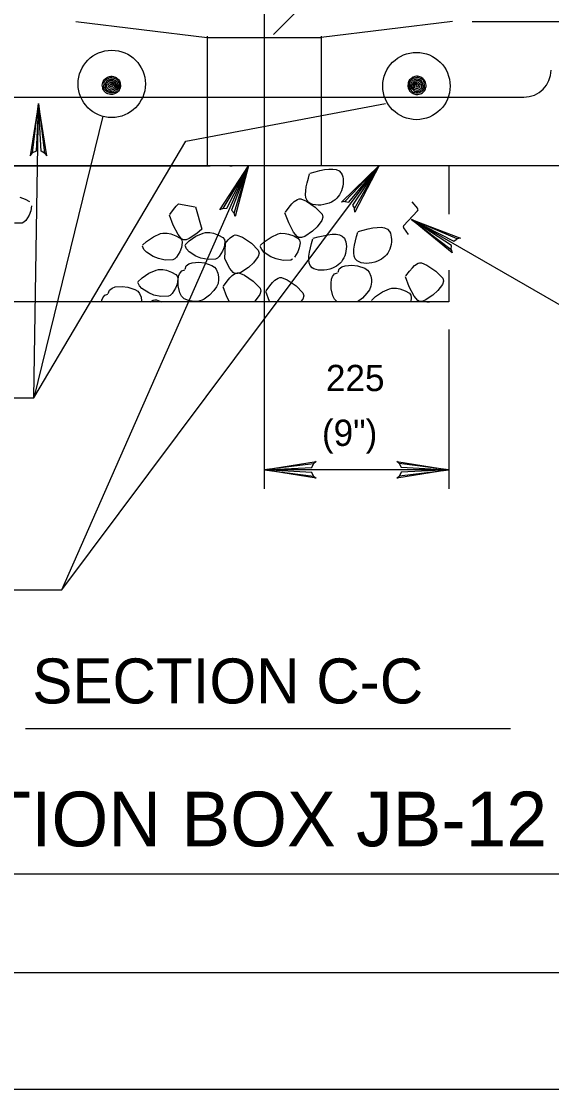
# Model space of a CAD drawing. Extents: x 638455 to 640199, y 298558 to 299152.
# Drawn here: x 639468.1 to 639536, y 298558.2 to 298695 of the extents above; entities that cross this region are included whole.
import ezdxf

# ---------------------------------------------------------------- set-up
doc = ezdxf.new("R2010")
doc.units = 0
for name, color, linetype in [('1', 7, 'Continuous'), ('2', 7, 'Continuous'), ('3', 7, 'Continuous'), ('PLT-BNDY', 7, 'Continuous')]:
    doc.layers.add(name, color=color, linetype=linetype)

msp = doc.modelspace()

# ---------------------------------------------------------------- linework, layer by layer
at = {"layer": '1'}
for p, q in [((639469.69, 298646.83), (639470.27, 298684.48)), ((639489.14, 298679.7), (639514.7, 298684.48)), ((639478.52, 298682.86), (639469.69, 298646.83)), ((639469.69, 298646.83), (639489.14, 298679.7)), ((639518.83, 298670.78), (639517.03, 298668.82)), ((639518.07, 298671.93), (639518.83, 298671.04)), ((639517.01, 298668.57), (639517.62, 298667.75))]:
    msp.add_line(p, q, dxfattribs=at)
msp.add_lwpolyline([(640119.61, 298573.25), (640119.61, 299137.25), (639333.61, 299137.25), (639333.61, 298573.25), (640119.61, 298573.25), (640119.61, 298599.61), (639919.61, 298599.61), (639919.61, 298664.29), (640119.61, 298664.29), (640119.61, 298693.25), (639919.61, 298693.25), (639919.61, 298573.25), (639998.42, 298573.25), (639998.42, 298599.61), (639998.42, 298573.25), (640075.42, 298573.25), (640075.42, 298599.61), (640075.42, 298587.29), (640119.61, 298587.29)], dxfattribs=at)
for centre in [(639479.66, 298687.01), (639518.68, 298686.74)]:
    msp.add_circle(centre, 4.31, dxfattribs=at)
for centre, start, end in [((639518.68, 298670.91), 317.4357, 40.7089), ((639517.18, 298668.68), 137.4357, 216.5044)]:
    msp.add_arc(centre, 0.2, start, end, dxfattribs=at)
at = {"layer": '2'}
for p, q in [((639500.37, 298693.34), (639515.41, 298708.39)), ((639499.18, 298704.79), (639499.18, 298643.37)), ((639475.08, 298695.02), (639491.9, 298692.96)), ((639523.29, 298695.02), (639506.47, 298692.96)), ((639525.82, 298695.02), (639581.13, 298695.02)), ((639491.9, 298693.11), (639491.9, 298676.53)), ((639491.9, 298692.96), (639506.47, 298692.96)), ((639506.47, 298693.11), (639506.47, 298676.53)), ((639465.64, 298685.31), (639532.43, 298685.31)), ((639543.38, 298676.53), (639454.98, 298676.53)), ((639457.42, 298676.53), (639492.28, 298676.53)), ((639473.27, 298622.22), (639497.18, 298676.53)), ((639494.8, 298676.53), (639495.08, 298676.53)), ((639522.81, 298676.53), (639522.81, 298670.34)), ((639554.38, 298648.67), (639518.04, 298669.66)), ((639522.81, 298663.17), (639522.81, 298659.11)), ((639522.81, 298659.11), (639414.14, 298659.11)), ((639522.81, 298655.56), (639522.81, 298635.17)), ((639460.96, 298646.83), (639469.69, 298646.83)), ((639499.18, 298643.37), (639499.18, 298635.17)), ((639522.81, 298637.61), (639499.18, 298637.61)), ((639464.54, 298622.22), (639473.27, 298622.22))]:
    msp.add_line(p, q, dxfattribs=at)
for points in [[(639471.07, 298678.15), (639470.61, 298678.38), (639470.27, 298684.48), (639471.07, 298678.15), (639471.35, 298677.82), (639470.27, 298684.48), (639469.97, 298678.39), (639469.52, 298678.17), (639470.27, 298684.48), (639469.22, 298677.82), (639469.52, 298678.17)], [(639473.27, 298622.22), (639513.92, 298676.56)], [(639493.9, 298671.06), (639494.41, 298671.09), (639497.18, 298676.53), (639493.9, 298671.06), (639493.51, 298670.88), (639497.18, 298676.53), (639495, 298670.84), (639495.32, 298670.45), (639497.18, 298676.53), (639495.46, 298670.02), (639495.32, 298670.45)], [(639509.49, 298671.97), (639510, 298671.88), (639513.92, 298676.56), (639509.49, 298671.97), (639509.07, 298671.88), (639513.92, 298676.56), (639510.51, 298671.5), (639510.74, 298671.05), (639513.92, 298676.56), (639510.78, 298670.6), (639510.74, 298671.05)], [(639467.91, 298672.51), (639468.57, 298672.27)], [(639468.57, 298672.27), (639469.12, 298671.97)], [(639503.01, 298671.94), (639503.44, 298672.23)], [(639503.44, 298672.23), (639503.66, 298672.29)], [(639503.66, 298672.29), (639503.87, 298672.28)], [(639503.87, 298672.28), (639504.58, 298672)], [(639469.28, 298670.75), (639469.08, 298670.22)], [(639469.37, 298671.42), (639469.28, 298670.75)], [(639487.11, 298670.3), (639487.57, 298670.92)], [(639487.57, 298670.92), (639487.93, 298671.36)], [(639487.93, 298671.36), (639488.22, 298671.65)], [(639488.22, 298671.65), (639490.34, 298671.26)], [(639490.37, 298671.26), (639491.19, 298668.42)], [(639501.9, 298670.59), (639502.36, 298671.21)], [(639502.36, 298671.21), (639502.72, 298671.66)], [(639502.72, 298671.66), (639503.01, 298671.94)], [(639504.58, 298672), (639505.72, 298671.22)], [(639505.72, 298671.22), (639506.6, 298670.34)], [(639468.65, 298669.54), (639468.42, 298669.31)], [(639469.08, 298670.22), (639468.65, 298669.54)], [(639487.53, 298668.93), (639487.06, 298670.21)], [(639502.32, 298669.22), (639501.84, 298670.51)], [(639506.57, 298669.52), (639505.97, 298668.71)], [(639506.71, 298669.94), (639506.57, 298669.52)], [(639506.6, 298670.34), (639506.71, 298669.94)], [(639523.12, 298665.81), (639523.15, 298666.32), (639518.04, 298669.66), (639523.12, 298665.81), (639523.27, 298665.4), (639518.04, 298669.66), (639523.46, 298666.87), (639523.88, 298667.16), (639518.04, 298669.66), (639524.33, 298667.25), (639523.88, 298667.16)], [(639468.19, 298669.19), (639467.21, 298669.16)], [(639468.42, 298669.31), (639468.19, 298669.19)], [(639488.17, 298667.72), (639487.53, 298668.93)], [(639491.19, 298668.42), (639490.56, 298667.84)], [(639502.95, 298668.01), (639502.32, 298669.22)], [(639503.4, 298667.47), (639502.95, 298668.01)], [(639505.35, 298668.14), (639504.37, 298667.49)], [(639505.97, 298668.71), (639505.35, 298668.14)], [(639483.59, 298666.35), (639484.11, 298666.85)], [(639484.11, 298666.85), (639484.99, 298667.43)], [(639484.99, 298667.43), (639485.9, 298667.84)], [(639485.9, 298667.84), (639486.19, 298667.92)], [(639486.19, 298667.92), (639486.77, 298667.91)], [(639486.77, 298667.91), (639487.23, 298667.82)], [(639487.23, 298667.82), (639487.88, 298667.58)], [(639487.88, 298667.58), (639488.43, 298667.28)], [(639488.61, 298667.18), (639488.17, 298667.72)], [(639488.43, 298667.28), (639488.62, 298667.03)], [(639488.69, 298666.72), (639488.59, 298666.05)], [(639488.86, 298667.03), (639488.61, 298667.18)], [(639488.62, 298667.03), (639488.69, 298666.72)], [(639489.17, 298667.04), (639488.86, 298667.03)], [(639489.05, 298666.41), (639489.57, 298666.92)], [(639489.58, 298667.2), (639489.17, 298667.04)], [(639489.57, 298666.92), (639490.45, 298667.5)], [(639490.56, 298667.84), (639489.58, 298667.2)], [(639490.45, 298667.5), (639491.36, 298667.91)], [(639491.36, 298667.91), (639491.65, 298667.98)], [(639491.65, 298667.98), (639492.23, 298667.97)], [(639492.23, 298667.97), (639492.69, 298667.88)], [(639492.69, 298667.88), (639493.34, 298667.64)], [(639493.34, 298667.64), (639493.89, 298667.34)], [(639493.89, 298667.34), (639494.09, 298667.1)], [(639494.15, 298666.78), (639494.05, 298666.12)], [(639494.09, 298667.1), (639494.15, 298666.78)], [(639494.15, 298664.6), (639494.22, 298666.63)], [(639494.18, 298666.59), (639494.55, 298667.04)], [(639494.55, 298667.04), (639494.83, 298667.32)], [(639494.83, 298667.32), (639495.26, 298667.61)], [(639495.26, 298667.61), (639495.48, 298667.67)], [(639495.48, 298667.67), (639495.69, 298667.66)], [(639495.69, 298667.66), (639496.4, 298667.38)], [(639496.4, 298667.38), (639497.54, 298666.6)], [(639498.67, 298666.31), (639499.2, 298666.81)], [(639499.2, 298666.81), (639500.07, 298667.39)], [(639500.07, 298667.39), (639500.98, 298667.8)], [(639500.98, 298667.8), (639501.28, 298667.88)], [(639501.28, 298667.88), (639501.86, 298667.87)], [(639501.86, 298667.87), (639502.31, 298667.78)], [(639502.31, 298667.78), (639502.96, 298667.54)], [(639502.96, 298667.54), (639503.51, 298667.24)], [(639503.64, 298667.33), (639503.4, 298667.47)], [(639503.51, 298667.24), (639503.71, 298666.99)], [(639503.95, 298667.34), (639503.64, 298667.33)], [(639503.77, 298666.68), (639503.67, 298666.01)], [(639503.71, 298666.99), (639503.77, 298666.68)], [(639504.37, 298667.49), (639503.95, 298667.34)], [(639483.79, 298665.83), (639483.59, 298666.24)], [(639484.1, 298665.47), (639483.79, 298665.83)], [(639484.96, 298664.91), (639484.1, 298665.47)], [(639488.39, 298665.52), (639487.97, 298664.84)], [(639488.59, 298666.05), (639488.39, 298665.52)], [(639489.25, 298665.89), (639489.05, 298666.3)], [(639489.57, 298665.53), (639489.25, 298665.89)], [(639490.43, 298664.97), (639489.57, 298665.53)], [(639493.85, 298665.59), (639493.43, 298664.91)], [(639494.05, 298666.12), (639493.85, 298665.59)], [(639497.54, 298666.6), (639498.42, 298665.72)], [(639498.53, 298665.32), (639498.39, 298664.9)], [(639498.42, 298665.72), (639498.53, 298665.32)], [(639498.87, 298665.79), (639498.67, 298666.2)], [(639499.19, 298665.43), (639498.87, 298665.79)], [(639500.05, 298664.87), (639499.19, 298665.43)], [(639503.47, 298665.49), (639503.05, 298664.81)], [(639503.67, 298666.01), (639503.47, 298665.49)], [(639485.63, 298664.65), (639484.96, 298664.91)], [(639486.52, 298664.46), (639485.63, 298664.65)], [(639487.5, 298664.49), (639486.52, 298664.46)], [(639487.73, 298664.61), (639487.5, 298664.49)], [(639487.97, 298664.84), (639487.73, 298664.61)], [(639489.21, 298663.71), (639489.55, 298663.96)], [(639489.55, 298663.96), (639489.96, 298664.1)], [(639489.96, 298664.1), (639490.83, 298664.17)], [(639491.09, 298664.72), (639490.43, 298664.97)], [(639490.83, 298664.17), (639491.53, 298664.09)], [(639491.99, 298664.53), (639491.09, 298664.72)], [(639491.53, 298664.09), (639492.47, 298663.78)], [(639492.96, 298664.56), (639491.99, 298664.53)], [(639493.19, 298664.68), (639492.96, 298664.56)], [(639493.43, 298664.91), (639493.19, 298664.68)], [(639494.78, 298663.39), (639494.15, 298664.6)], [(639497.8, 298664.09), (639497.17, 298663.52)], [(639498.39, 298664.9), (639497.8, 298664.09)], [(639500.71, 298664.61), (639500.05, 298664.87)], [(639501.61, 298664.42), (639500.71, 298664.61)], [(639502.58, 298664.45), (639501.61, 298664.42)], [(639502.81, 298664.57), (639502.58, 298664.45)], [(639518.45, 298663.76), (639518.88, 298664.05)], [(639518.88, 298664.05), (639519.09, 298664.12)], [(639519.09, 298664.12), (639519.31, 298664.1)], [(639519.31, 298664.1), (639520.02, 298663.82)], [(639483.54, 298662.18), (639484.42, 298662.76)], [(639484.42, 298662.76), (639485.33, 298663.17)], [(639485.33, 298663.17), (639485.63, 298663.25)], [(639485.63, 298663.25), (639486.2, 298663.24)], [(639486.2, 298663.24), (639486.66, 298663.15)], [(639486.66, 298663.15), (639487.31, 298662.91)], [(639487.31, 298662.91), (639487.86, 298662.61)], [(639487.86, 298662.61), (639488.06, 298662.36)], [(639488.23, 298662.39), (639488.35, 298662.71)], [(639488.35, 298662.71), (639488.62, 298663.06)], [(639488.62, 298663.06), (639489, 298663.2)], [(639489.06, 298663.28), (639489.21, 298663.71)], [(639492.47, 298663.78), (639492.82, 298663.55)], [(639492.82, 298663.55), (639493.05, 298663.28)], [(639493.05, 298663.28), (639493.25, 298662.77)], [(639493.25, 298662.77), (639493.33, 298662.33)], [(639495.22, 298662.85), (639494.78, 298663.39)], [(639495.08, 298662.47), (639495.51, 298662.76)], [(639495.47, 298662.71), (639495.22, 298662.85)], [(639495.77, 298662.72), (639495.47, 298662.71)], [(639495.51, 298662.76), (639495.73, 298662.82)], [(639495.73, 298662.82), (639495.94, 298662.81)], [(639496.19, 298662.88), (639495.77, 298662.72)], [(639495.94, 298662.81), (639496.65, 298662.52)], [(639497.17, 298663.52), (639496.19, 298662.88)], [(639496.65, 298662.52), (639497.79, 298661.74)], [(639507.93, 298662.34), (639508.2, 298662.69)], [(639508.2, 298662.69), (639508.58, 298662.83)], [(639508.64, 298662.91), (639508.79, 298663.34)], [(639508.79, 298663.34), (639509.13, 298663.59)], [(639509.13, 298663.59), (639509.54, 298663.73)], [(639509.54, 298663.73), (639510.41, 298663.8)], [(639510.41, 298663.8), (639511.11, 298663.72)], [(639511.11, 298663.72), (639512.05, 298663.41)], [(639512.05, 298663.41), (639512.4, 298663.18)], [(639512.4, 298663.18), (639512.64, 298662.91)], [(639512.64, 298662.91), (639512.83, 298662.4)], [(639517.34, 298662.42), (639517.79, 298663.03)], [(639517.79, 298663.03), (639518.16, 298663.48)], [(639518.16, 298663.48), (639518.45, 298663.76)], [(639520.02, 298663.82), (639521.16, 298663.04)], [(639521.16, 298663.04), (639522.04, 298662.16)], [(639483.02, 298661.68), (639483.54, 298662.18)], [(639483.22, 298661.16), (639483.02, 298661.57)], [(639483.53, 298660.8), (639483.22, 298661.16)], [(639488.02, 298661.38), (639487.82, 298660.85)], [(639488.12, 298662.05), (639488.02, 298661.38)], [(639488.06, 298662.36), (639488.12, 298662.05)], [(639488.15, 298661.89), (639488.23, 298662.39)], [(639488.17, 298661.16), (639488.15, 298661.89)], [(639488.38, 298660.24), (639488.17, 298661.16)], [(639493.27, 298661.47), (639493.08, 298661.03)], [(639493.34, 298661.98), (639493.27, 298661.47)], [(639493.33, 298662.33), (639493.34, 298661.98)], [(639493.97, 298661.12), (639494.42, 298661.74)], [(639494.42, 298661.74), (639494.79, 298662.18)], [(639494.79, 298662.18), (639495.08, 298662.47)], [(639497.79, 298661.74), (639498.67, 298660.87)], [(639499.89, 298661.14), (639500.26, 298661.59)], [(639500.26, 298661.59), (639500.54, 298661.87)], [(639500.54, 298661.87), (639500.98, 298662.16)], [(639500.98, 298662.16), (639501.19, 298662.22)], [(639501.19, 298662.22), (639501.41, 298662.21)], [(639501.41, 298662.21), (639502.12, 298661.93)], [(639502.12, 298661.93), (639503.26, 298661.14)], [(639507.74, 298661.52), (639507.81, 298662.02)], [(639507.75, 298660.79), (639507.74, 298661.52)], [(639507.81, 298662.02), (639507.93, 298662.34)], [(639512.83, 298662.4), (639512.91, 298661.95)], [(639512.92, 298661.61), (639512.85, 298661.1)], [(639512.91, 298661.95), (639512.92, 298661.61)], [(639517.76, 298661.05), (639517.28, 298662.33)], [(639522.01, 298661.34), (639521.41, 298660.54)], [(639522.14, 298661.77), (639522.01, 298661.34)], [(639522.04, 298662.16), (639522.14, 298661.77)], [(639478.51, 298659.63), (639478.78, 298659.97)], [(639478.78, 298659.97), (639479.16, 298660.11)], [(639479.22, 298660.19), (639479.37, 298660.62)], [(639479.37, 298660.62), (639479.71, 298660.87)], [(639479.71, 298660.87), (639480.12, 298661.01)], [(639480.12, 298661.01), (639481, 298661.08)], [(639481, 298661.08), (639481.7, 298661)], [(639481.7, 298661), (639482.63, 298660.69)], [(639482.63, 298660.69), (639482.99, 298660.46)], [(639482.99, 298660.46), (639483.22, 298660.19)], [(639483.22, 298660.19), (639483.42, 298659.69)], [(639484.39, 298660.24), (639483.53, 298660.8)], [(639485.06, 298659.98), (639484.39, 298660.24)], [(639485.96, 298659.79), (639485.06, 298659.98)], [(639486.93, 298659.82), (639485.96, 298659.79)], [(639487.16, 298659.94), (639486.93, 298659.82)], [(639487.4, 298660.17), (639487.16, 298659.94)], [(639487.82, 298660.85), (639487.4, 298660.17)], [(639488.6, 298659.82), (639488.38, 298660.24)], [(639488.92, 298659.51), (639488.6, 298659.82)], [(639492.17, 298659.97), (639491.51, 298659.45)], [(639492.75, 298660.58), (639492.17, 298659.97)], [(639493.08, 298661.03), (639492.75, 298660.58)], [(639494.39, 298659.75), (639493.91, 298661.03)], [(639498.64, 298660.05), (639498.04, 298659.24)], [(639498.77, 298660.47), (639498.64, 298660.05)], [(639498.67, 298660.87), (639498.77, 298660.47)], [(639499.85, 298659.15), (639499.38, 298660.44)], [(639499.43, 298660.52), (639499.89, 298661.14)], [(639503.26, 298661.14), (639504.14, 298660.27)], [(639504.24, 298659.87), (639504.11, 298659.45)], [(639504.14, 298660.27), (639504.24, 298659.87)], [(639507.97, 298659.87), (639507.75, 298660.79)], [(639508.18, 298659.45), (639507.97, 298659.87)], [(639512.33, 298660.21), (639511.75, 298659.59)], [(639512.66, 298660.66), (639512.33, 298660.21)], [(639512.85, 298661.1), (639512.66, 298660.66)], [(639512.93, 298659.29), (639513.45, 298659.79)], [(639513.45, 298659.79), (639514.33, 298660.38)], [(639514.33, 298660.38), (639515.23, 298660.79)], [(639515.23, 298660.79), (639515.53, 298660.86)], [(639515.53, 298660.86), (639516.11, 298660.85)], [(639516.11, 298660.85), (639516.56, 298660.76)], [(639516.56, 298660.76), (639517.22, 298660.52)], [(639517.22, 298660.52), (639517.77, 298660.22)], [(639518.39, 298659.83), (639517.76, 298661.05)], [(639517.77, 298660.22), (639517.96, 298659.98)], [(639517.96, 298659.98), (639518.02, 298659.66)], [(639518.84, 298659.3), (639518.39, 298659.83)], [(639520.78, 298659.96), (639519.81, 298659.31)], [(639521.41, 298660.54), (639520.78, 298659.96)], [(639478.37, 298659.11), (639478.4, 298659.31)], [(639478.4, 298659.31), (639478.51, 298659.63)], [(639483.42, 298659.69), (639483.49, 298659.24)], [(639483.49, 298659.24), (639483.5, 298659.11)], [(639484.64, 298659.11), (639484.95, 298659.32)], [(639484.95, 298659.32), (639485.17, 298659.38)], [(639485.17, 298659.38), (639485.38, 298659.37)], [(639485.38, 298659.37), (639486.04, 298659.11)], [(639489.49, 298659.28), (639488.92, 298659.51)], [(639490.17, 298659.16), (639489.49, 298659.28)], [(639490.63, 298659.17), (639490.17, 298659.16)], [(639491.22, 298659.31), (639490.63, 298659.17)], [(639491.51, 298659.45), (639491.22, 298659.31)], [(639494.72, 298659.11), (639494.39, 298659.75)], [(639498.04, 298659.24), (639497.9, 298659.11)], [(639499.88, 298659.11), (639499.85, 298659.15)], [(639504.11, 298659.45), (639503.85, 298659.11)], [(639508.5, 298659.14), (639508.18, 298659.45)], [(639508.57, 298659.11), (639508.5, 298659.14)], [(639511.75, 298659.59), (639511.12, 298659.11)], [(639512.96, 298659.11), (639512.93, 298659.18)], [(639518.02, 298659.66), (639517.94, 298659.11)], [(639519.08, 298659.15), (639518.84, 298659.3)], [(639519.39, 298659.16), (639519.08, 298659.15)], [(639519.81, 298659.31), (639519.39, 298659.16)], [(639519.99, 298659.11), (639520, 298659.11)], [(639520, 298659.11), (639520.34, 298659.11)], [(639505.51, 298636.81), (639505.28, 298637.27), (639499.18, 298637.61), (639505.51, 298636.81), (639505.84, 298636.53), (639499.18, 298637.61), (639505.27, 298637.91), (639505.49, 298638.36), (639499.18, 298637.61), (639505.84, 298638.67), (639505.49, 298638.36)], [(639516.48, 298638.4), (639516.72, 298637.94), (639522.81, 298637.61), (639516.48, 298638.4), (639516.16, 298638.68), (639522.81, 298637.61), (639516.73, 298637.31), (639516.5, 298636.85), (639522.81, 298637.61), (639516.16, 298636.55), (639516.5, 298636.85)]]:
    msp.add_lwpolyline(points, dxfattribs=at)
msp.add_arc((639532.43, 298688.79), 3.48, 270, 0, dxfattribs=at)
for points in [[(639479.62, 298686.82), (639479.68, 298686.93), (639479.77, 298686.92), (639479.79, 298686.74), (639479.63, 298686.64), (639479.43, 298686.74), (639479.44, 298686.92), (639479.55, 298687.03), (639479.77, 298687.05), (639479.92, 298686.93), (639480, 298686.75), (639479.88, 298686.5), (639479.64, 298686.44), (639479.38, 298686.52), (639479.23, 298686.69), (639479.25, 298686.98), (639479.38, 298687.16), (639479.63, 298687.23), (639479.84, 298687.18), (639480.02, 298687.08), (639480.1, 298686.89), (639480.14, 298686.65), (639480.08, 298686.43), (639479.87, 298686.28), (639479.56, 298686.22), (639479.21, 298686.36), (639479.03, 298686.6), (639479.03, 298686.93), (639479.14, 298687.22), (639479.38, 298687.4), (639479.77, 298687.42), (639480.04, 298687.27), (639480.21, 298687.01), (639480.3, 298686.74), (639480.26, 298686.41), (639480.04, 298686.18), (639479.72, 298686.04), (639479.22, 298686.12), (639478.9, 298686.4), (639478.84, 298686.78), (639478.9, 298687.16), (639479.12, 298687.46), (639479.42, 298687.58), (639479.87, 298687.57), (639480.24, 298687.36), (639480.41, 298687.05), (639480.46, 298686.72), (639480.42, 298686.44), (639480.31, 298686.14), (639480.02, 298685.93), (639479.54, 298685.86), (639479.11, 298685.98), (639478.79, 298686.27), (639478.66, 298686.62), (639478.69, 298687.06), (639478.84, 298687.48), (639479.08, 298687.65), (639479.5, 298687.81), (639479.94, 298687.74), (639480.25, 298687.6), (639480.49, 298687.33), (639480.61, 298687.04), (639480.61, 298686.74), (639480.6, 298686.41), (639480.52, 298686.1), (639480.37, 298685.93), (639480.12, 298685.78), (639479.88, 298685.69), (639479.64, 298685.65), (639479.34, 298685.69), (639479.03, 298685.79), (639478.77, 298685.99), (639478.59, 298686.24), (639478.5, 298686.55), (639478.45, 298686.84), (639478.52, 298687.18), (639478.64, 298687.46), (639478.86, 298687.71), (639479.12, 298687.87), (639479.38, 298687.97), (639479.7, 298687.98), (639480.06, 298687.89), (639480.37, 298687.71), (639480.55, 298687.51), (639480.71, 298687.26), (639480.76, 298687), (639480.77, 298686.69), (639480.71, 298686.36), (639480.61, 298686.21), (639480.41, 298685.99)], [(639518.75, 298686.82), (639518.69, 298686.93), (639518.6, 298686.92), (639518.58, 298686.74), (639518.74, 298686.64), (639518.94, 298686.74), (639518.93, 298686.92), (639518.82, 298687.03), (639518.6, 298687.05), (639518.45, 298686.93), (639518.37, 298686.75), (639518.48, 298686.5), (639518.72, 298686.44), (639518.99, 298686.52), (639519.13, 298686.69), (639519.12, 298686.98), (639518.98, 298687.16), (639518.74, 298687.23), (639518.53, 298687.18), (639518.35, 298687.08), (639518.27, 298686.89), (639518.23, 298686.65), (639518.28, 298686.43), (639518.49, 298686.28), (639518.81, 298686.22), (639519.16, 298686.36), (639519.33, 298686.6), (639519.33, 298686.93), (639519.22, 298687.22), (639518.98, 298687.4), (639518.6, 298687.42), (639518.33, 298687.27), (639518.16, 298687.01), (639518.06, 298686.74), (639518.11, 298686.41), (639518.33, 298686.18), (639518.64, 298686.04), (639519.15, 298686.12), (639519.47, 298686.4), (639519.53, 298686.78), (639519.47, 298687.16), (639519.24, 298687.46), (639518.95, 298687.58), (639518.49, 298687.57), (639518.13, 298687.36), (639517.96, 298687.05), (639517.91, 298686.72), (639517.94, 298686.44), (639518.05, 298686.14), (639518.35, 298685.93), (639518.83, 298685.86), (639519.26, 298685.98), (639519.58, 298686.27), (639519.71, 298686.62), (639519.67, 298687.06), (639519.53, 298687.48), (639519.29, 298687.65), (639518.87, 298687.81), (639518.43, 298687.74), (639518.12, 298687.6), (639517.88, 298687.33), (639517.75, 298687.04), (639517.75, 298686.74), (639517.77, 298686.41), (639517.84, 298686.1), (639518, 298685.93), (639518.24, 298685.78), (639518.48, 298685.69), (639518.72, 298685.65), (639519.03, 298685.69), (639519.33, 298685.79), (639519.6, 298685.99), (639519.78, 298686.24), (639519.87, 298686.55), (639519.92, 298686.84), (639519.85, 298687.18), (639519.73, 298687.46), (639519.51, 298687.71), (639519.24, 298687.87), (639518.98, 298687.97), (639518.67, 298687.98), (639518.3, 298687.89), (639518, 298687.71), (639517.81, 298687.51), (639517.66, 298687.26), (639517.6, 298687), (639517.59, 298686.69), (639517.66, 298686.36), (639517.75, 298686.21), (639517.96, 298685.99)], [(639505.06, 298675.58), (639509.05, 298675.58), (639509.08, 298673.33), (639507.51, 298671.75), (639504.91, 298671.81), (639505, 298675.5)], [(639505.46, 298667.24), (639509.46, 298667.24), (639509.49, 298664.99), (639507.91, 298663.42), (639505.32, 298663.47), (639505.4, 298667.16)], [(639511.23, 298668.12), (639515.23, 298668.12), (639515.26, 298665.87), (639513.68, 298664.3), (639511.09, 298664.35), (639511.17, 298668.04)]]:
    msp.add_spline(points, degree=3, dxfattribs=at)
at = {"layer": '3'}
for p, q in [((639468.61, 298604.5), (639530.74, 298604.5)), ((639435.78, 298585.86), (639565.11, 298585.86))]:
    msp.add_line(p, q, dxfattribs=at)
at = {"layer": 'PLT-BNDY'}
msp.add_lwpolyline([(639295.61, 299152.25), (640136.61, 299152.25), (640136.61, 298558.25), (639295.61, 298558.25)], close=True, dxfattribs=at)

# ---------------------------------------------------------------- texts
at = {"layer": '1'}
msp.add_text('(9")', height=3.36, dxfattribs=at).set_placement((639506.58, 298640.66))
at = {"layer": '3'}
for s, height, p in [('225', 3.36, (639507.09, 298647.68)), ('SECTION C-C', 5.76, (639469.48, 298607.69)), ('JUNCTION BOX JB-12', 7, (639438.66, 298589.4))]:
    msp.add_text(s, height=height, dxfattribs=at).set_placement(p)

doc.saveas('drawing.dxf')
